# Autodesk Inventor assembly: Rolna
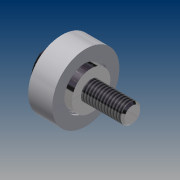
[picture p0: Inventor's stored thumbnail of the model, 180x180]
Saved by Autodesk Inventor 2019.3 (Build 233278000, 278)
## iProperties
Created: 2019-01
Part Number: Rolna
Material: Všeobecné
Document SubType Name: Assembly
Designer: B-hon
Author: B-hon
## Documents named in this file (4)
- C:\Users\B-hon\OneDrive\Plocha\Bakalářka22\Rolna.iam
- C:\Users\B-hon\OneDrive\Plocha\Bakalářka22\Rolna.ipt
- C:\Users\B-hon\OneDrive\Documents\Inventor\Content Center Files\R2019\cs-CZ\DIN 125-1  A\DIN 125 - A 8,4.ipt
- C:\Users\B-hon\OneDrive\Documents\Inventor\Content Center Files\R2019\cs-CZ\DIN 933\DIN 933 - M8  x 30.ipt
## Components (5 placed, 3 different names)
1. Rolna:1 — Vložit:1, Vložit:3
2. DIN 125-1 A A 8,4:1 — Vložit:1, Vložit:2
3. DIN 125-1 A A 8,4:2 — Vložit:2
4. DIN 125-1 A A 8,4:3 — Vložit:3, Vložit:4
5. DIN 933 - nahrazený DIN EN 24017 M8  x 30:1 — Vložit:4
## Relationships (4: Insert 4)
- Vložit:1 [Insert]: Rolna:1 ↔ DIN 125-1 A A 8,4:1
- Vložit:2 [Insert]: DIN 125-1 A A 8,4:1 ↔ DIN 125-1 A A 8,4:2
- Vložit:3 [Insert]: Rolna:1 ↔ DIN 125-1 A A 8,4:3
- Vložit:4 [Insert]: DIN 125-1 A A 8,4:3 ↔ DIN 933 - nahrazený DIN EN 24017 M8  x 30:1
